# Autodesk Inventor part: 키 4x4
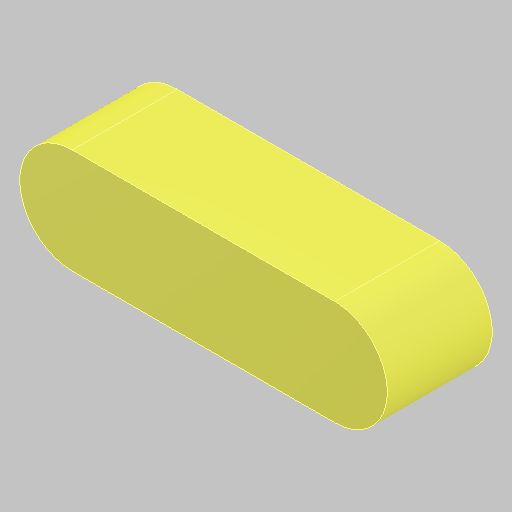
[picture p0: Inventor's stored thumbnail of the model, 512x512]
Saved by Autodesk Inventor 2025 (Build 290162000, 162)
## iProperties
Created: 2024-08
Part Number: 키 4x4
Material: 강철, 연강
Document SubType Name: Modeling
Designer: 현기
Density: 7.86 g/cm^3
Appearance: 기본값
Author: jhkim
Sending System: Autodesk Inventor 2025
Preprocessor: ST-DEVELOPER v20
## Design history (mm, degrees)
feature "솔리드1"
node "솔리드2"
